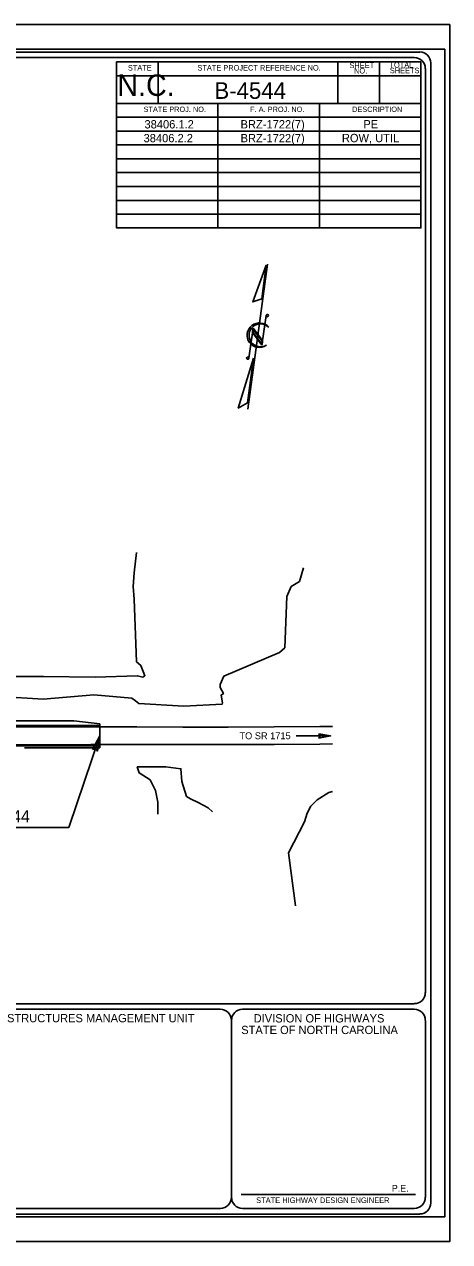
# Model space of a CAD drawing. Extents: x 0 to 2021, y 0 to 1321.
# Drawn here: x 1560 to 2021, y 0 to 1321 of the extents above; entities that cross this region are included whole.
import ezdxf

# ---------------------------------------------------------------- set-up
doc = ezdxf.new("R2010")
doc.units = 0
for name, color, linetype in [('Default', 7, 'Continuous'), ('Dimension Lines', 7, 'Continuous'), ('Exist Hydro Stream or Body of Water', 7, 'Continuous'), ('Exist Roads EOP', 7, 'Continuous'), ('Prop EOT', 7, 'Continuous'), ('Sheet Data Field CELL', 7, 'Continuous'), ('Sheet North Arrow CELL', 7, 'Continuous'), ('Sheet Plot Border Inside CELL', 7, 'Continuous'), ('Sheet Plot Border Outside CELL', 7, 'Continuous'), ('Sheet Title CELL', 7, 'Continuous'), ('Text', 7, 'Continuous')]:
    doc.layers.add(name, color=color, linetype=linetype)

msp = doc.modelspace()

# ---------------------------------------------------------------- linework, layer by layer
at = {"layer": 'Default'}
for p, q in [((1502.9, 564.9), (1613.5, 564.9)), ((1502.9, 564.9), (1613.5, 564.9)), ((1613.5, 564.9), (1641.6, 561.9)), ((1613.5, 564.9), (1641.6, 561.9)), ((1641.6, 561.9), (1641.6, 535.9)), ((1641.6, 561.9), (1641.6, 559.9)), ((1892, 548.6), (1854.6, 548.6)), ((1641.6, 535.9), (1559.9, 535.9)), ((1559.9, 535.9), (1641.6, 535.9)), ((1641.6, 537.9), (1641.6, 535.9))]:
    msp.add_line(p, q, dxfattribs=at)
for points in [[(1633.7, 534.1), (1641.6, 548.9), (1639.2, 532.2), (1637, 535.1)], [(1879.4, 550.8), (1892, 548.6), (1879.3, 546.4), (1880.9, 548.6)]]:
    msp.add_lwpolyline(points, close=True, dxfattribs=at)
at = {"layer": 'Dimension Lines'}
for p, q in [((1641.6, 548.9), (1608.3, 449.3)), ((1608.3, 449.3), (1343, 449.3))]:
    msp.add_line(p, q, dxfattribs=at)
at = {"layer": 'Exist Hydro Stream or Body of Water'}
for points in [[(1681.6, 628.9), (1679, 697), (1678, 710.9), (1678.9, 725.5), (1681.4, 747.5)], [(1842.3, 644.3), (1844.6, 699.8), (1849.3, 710.7), (1858.4, 716.2), (1862.6, 731)], [(1429, 567.6), (1432.9, 575), (1436, 578.9), (1440.9, 581.2), (1449.4, 584.6), (1484.6, 586.2), (1533.6, 591.4), (1580.2, 588.6), (1635.2, 593.2), (1676.5, 589.5), (1680.5, 586.7), (1684, 583.8), (1733, 580.8), (1774.3, 583), (1774.8, 584.4), (1773.2, 593), (1775.8, 594.6), (1772.2, 601.2), (1772.2, 604.6), (1776.1, 613.6), (1836.6, 639), (1842.3, 644.3)], [(1636.7, 612.3), (1580.5, 613.2), (1532.6, 613), (1488.7, 616.1), (1444.2, 609.6), (1438.9, 610.9), (1437.9, 613.4), (1439, 617.7), (1441.7, 622.4), (1447.6, 630.2), (1453.7, 634.4), (1456.1, 639.7)], [(1636.7, 612.3), (1682.7, 614), (1688.4, 612.4), (1690.6, 614), (1686.4, 625), (1681.6, 628.9)], [(1704.7, 463.6), (1704.8, 476.8), (1702.3, 489.6), (1696.4, 500.9), (1684.3, 508.5), (1682.3, 515.1), (1713.4, 515.3), (1729.7, 513), (1730.6, 499.3), (1735.6, 483), (1740.1, 480.5), (1748.5, 476.6), (1759.1, 470.7), (1764, 466.4)], [(1863.7, 455.6), (1866.6, 464.9), (1870.5, 472.4), (1877.6, 479.2), (1890.3, 487.1), (1894, 488.4)], [(1863.7, 455.6), (1846.3, 421.9), (1853.8, 364.4)]]:
    msp.add_lwpolyline(points, dxfattribs=at)
at = {"layer": 'Exist Roads EOP'}
for points in [[(1432.3, 549), (1432.3, 558.5), (1483.3, 558.8), (1532.5, 558.6), (1582.3, 558.5), (1632.3, 558.5), (1681.9, 558.6), (1731.9, 558.3), (1780.9, 558.3), (1831, 558.5), (1880.4, 558.8), (1894, 558.8)], [(1432.3, 549), (1432.2, 539.3), (1483, 539.2), (1532.5, 539), (1582.6, 539.1), (1632.1, 539.3), (1681.7, 539.5), (1731.7, 539.5), (1781.1, 539.4), (1830.8, 539.3), (1880.3, 539.8), (1894, 539.9)]]:
    msp.add_lwpolyline(points, dxfattribs=at)
at = {"layer": 'Prop EOT'}
for p, q in [((751.5, 559.9), (1641.6, 559.9)), ((1641.6, 559.9), (1641.6, 537.9)), ((751.5, 537.9), (1641.6, 537.9))]:
    msp.add_line(p, q, dxfattribs=at)
at = {"layer": 'Sheet North Arrow CELL'}
for p, q in [((1802.1, 903), (1823.6, 1060.4)), ((1822, 1004.8), (1817.6, 972.5)), ((1807.9, 991.2), (1803.5, 958.4)), ((1818.3, 977.5), (1807.9, 991.2)), ((1824.9, 992.2), (1825, 992)), ((1817.6, 972.5), (1807.2, 986.2)), ((1807.8, 990), (1807.4, 987.1)), ((1817.8, 973.4), (1807.4, 987.1)), ((1807.4, 987.1), (1817.8, 973.4)), ((1818.2, 976.4), (1807.8, 990)), ((1817.8, 973.4), (1818.2, 976.4))]:
    msp.add_line(p, q, dxfattribs=at)
for points in [[(1822.3, 1059.2), (1807.7, 1019.5), (1817.3, 1022.8)], [(1808.4, 958.6), (1791.9, 904.4), (1801.8, 910.2)]]:
    msp.add_lwpolyline(points, close=True, dxfattribs=at)
for centre in [(1823.3, 1004.6), (1802.2, 958.5)]:
    msp.add_ellipse(centre, major_axis=(-0.28, 1.27), ratio=0.999692, dxfattribs=at)
for centre, major_axis, start_param, end_param in [((1814.8, 983.4), (2.8, -13), 2.056008, 6.673347), ((1816.1, 983.3), (2.7, -12.2), 2.147726, 6.60763)]:
    msp.add_ellipse(centre, major_axis=major_axis, ratio=0.999692, start_param=start_param, end_param=end_param, dxfattribs=at)
at = {"layer": 'Sheet Plot Border Inside CELL'}
msp.add_lwpolyline([(15.6, 26.9), (2015.8, 26.9), (2015.8, 1293.7), (15.6, 1293.7)], close=True, dxfattribs=at)
at = {"layer": 'Sheet Plot Border Outside CELL'}
msp.add_lwpolyline([(2021.2, 1320.6), (0, 1320.6), (0, 0), (2021.2, 0)], close=True, dxfattribs=at)
at = {"layer": 'Sheet Title CELL'}
for p, q in [((278.5, 258.1), (1982.8, 258.1)), ((1532.7, 252.1), (1772.4, 252.1)), ((1796.5, 252.1), (1982.8, 252.1)), ((1784.4, 48), (1784.4, 240.1)), ((1795.1, 51), (1984, 51))]:
    msp.add_line(p, q, dxfattribs=at)
for points in [[(1988.8, 1290.6), (212.4, 1290.6)], [(1982.8, 1284.6), (278.5, 1284.6)], [(1659.9, 1099.7), (1990, 1099.7), (1990, 1114.7), (1659.9, 1114.7), (1659.9, 1129.7), (1990, 1129.7), (1990, 1144.7), (1659.9, 1144.7), (1659.9, 1159.8), (1990, 1159.8), (1990, 1174.8), (1659.9, 1174.8), (1659.9, 1189.8), (1990, 1189.8), (1990, 1204.8), (1659.9, 1204.8), (1659.9, 1219.8), (1990, 1219.8), (1990, 1234.8), (1659.9, 1234.8), (1659.9, 1264.8), (1990, 1264.8), (1990, 1279.8), (1659.9, 1279.8), (1659.9, 1099.7), (1769.9, 1099.7), (1769.9, 1234.8), (1704.9, 1234.8), (1704.9, 1279.8), (1900, 1279.8), (1899.9, 1234.8), (1879.9, 1234.8), (1879.9, 1099.7), (1990, 1099.7), (1990, 1279.8), (1945, 1279.8), (1945, 1234.8)], [(1994.8, 270.1), (1994.8, 1272.6)], [(2000.8, 42), (2000.8, 1278.6)], [(1994.8, 48), (1994.8, 240.1)], [(212.4, 30), (1988.8, 30)], [(1532.7, 36), (1772.5, 36)], [(1796.5, 36), (1982.8, 36)]]:
    msp.add_lwpolyline(points, dxfattribs=at)
for centre, major_axis, start_param, end_param in [((1982.8, 1272.7), (0, 12), 4.712389, 6.283185), ((1988.8, 1278.7), (0, 12), 4.712389, 6.283185), ((1982.8, 270.2), (0, 12), 3.141593, 4.712389), ((1772.4, 240.1), (0, 12), 4.712389, 6.283185), ((1796.5, 240.1), (0, 12), 0, 1.570796), ((1982.8, 240.2), (0, 12), 4.712389, 6.283185), ((1772.5, 48.1), (0, 12), 3.141593, 4.712389), ((1796.5, 48.1), (0, -12), 4.712389, 6.283185), ((1982.8, 48.1), (0, -12), 0, 1.570796), ((1988.8, 42.1), (0, -12), 0, 1.570796)]:
    msp.add_ellipse(centre, major_axis=major_axis, ratio=0.999692, start_param=start_param, end_param=end_param, dxfattribs=at)

# ---------------------------------------------------------------- texts
at = {"layer": 'Dimension Lines'}
msp.add_text('P.E.', height=7.26, dxfattribs=at).set_placement((1958.4, 54.3))
at = {"layer": 'Sheet Data Field CELL'}
for s, height, p in [('B-4544', 18.01, (1766, 1239.8)), ('PE', 9, (1927.6, 1207.8)), ('ROW, UTIL', 9, (1904.3, 1192.8))]:
    msp.add_text(s, height=height, dxfattribs=at).set_placement(p)
for s, height, p in [('38406.1.2', 9, (1690.2, 1207.7)), ('BRZ-1722(7)', 9.004, (1794.4, 1207.7)), ('38406.2.2', 9, (1689.2, 1192.7)), ('BRZ-1722(7)', 9.004, (1794.4, 1192.7))]:
    msp.add_text(s, height=height, rotation=360, dxfattribs=at).set_placement(p)
at = {"layer": 'Sheet Title CELL'}
for s, height, p in [('STATE', 6, (1672.2, 1270.5)), ('STATE PROJECT REFERENCE NO.', 6.003, (1747.6, 1270.5)), ('SHEET', 6, (1912.5, 1273.2)), ('NO.', 6, (1917.5, 1267.3)), ('TOTAL', 6, (1955.9, 1273.6)), ('SHEETS', 6, (1956.3, 1267.6)), ('N.C.', 23.23, (1660.8, 1243)), ('STATE PROJ. NO.', 5.763, (1689.2, 1225.6)), ('F. A. PROJ. NO.', 5.763, (1804.8, 1225.6)), ('DESCRIPTION', 5.763, (1915.4, 1225.6)), ('STRUCTURES MANAGEMENT UNIT', 9.004, (1541.1, 238)), ('DIVISION OF HIGHWAYS', 9.004, (1808.6, 237.8)), ('STATE OF NORTH CAROLINA', 9.004, (1795.1, 225.2))]:
    msp.add_text(s, height=height, dxfattribs=at).set_placement(p)
msp.add_text('STATE HIGHWAY DESIGN ENGINEER', height=6.048, rotation=360, dxfattribs=at).set_placement((1811.3, 41.9))
at = {"layer": 'Text'}
msp.add_text('TO SR 1715', height=7.47, dxfattribs=at).set_placement((1793.2, 545.1))
msp.add_text('END TIP PROJECT B-4544', height=13.119, rotation=0.007, dxfattribs=at).set_placement((1348.5, 454.8))

doc.saveas('drawing.dxf')
